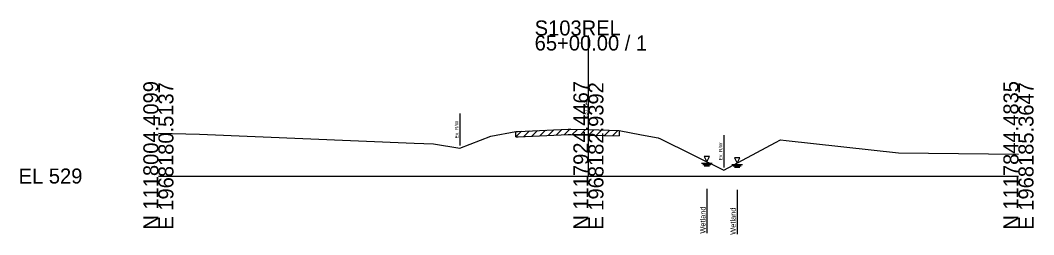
# Model space of a CAD drawing. Extents: x -26 to 163, y -10 to 24518.
# Drawn here: x -25.7 to 162.8, y 13489.1 to 13529 of the extents above; entities that cross this region are included whole.
import ezdxf

# ---------------------------------------------------------------- set-up
doc = ezdxf.new("R2010")
doc.units = 0
for name, color, linetype in [('RD_GPK_XS_Cell', 7, 'Continuous'), ('RD_XS_ExGround', 7, 'Continuous'), ('RD_XS_ExPaveRet', 7, 'Continuous'), ('RD_XS_ExRW', 7, 'Continuous'), ('RD_XS_EXWetland', 7, 'Continuous'), ('RD_XS_TX_Elev_EX', 7, 'Continuous')]:
    doc.layers.add(name, color=color, linetype=linetype)

msp = doc.modelspace()

# ---------------------------------------------------------------- linework, layer by layer
at = {"layer": 'RD_GPK_XS_Cell'}
for p, q in [((80, 13500), (80, 13526.18)), ((0, 13500), (80, 13500)), ((80, 13500), (160, 13500))]:
    msp.add_line(p, q, dxfattribs=at)
at = {"layer": 'RD_XS_ExGround'}
msp.add_lwpolyline([(0, 13507.96), (7.66, 13507.79), (47.56, 13506.15), (51.17, 13505.98), (56.06, 13505.16), (61.87, 13507.4), (66.48, 13508.3), (66.93, 13508.32), (76.24, 13508.73), (76.73, 13508.72), (80, 13508.64), (85.71, 13508.5), (89.89, 13507.7), (93, 13507.09), (93.41, 13506.91), (105.17, 13501.08), (114.83, 13506.25), (115.76, 13506.77), (116.78, 13506.6), (137.7, 13504.3), (160, 13504.08)], dxfattribs=at)
at = {"layer": 'RD_XS_ExPaveRet'}
for p, q in [((67.98, 13507.36), (69.03, 13508.41)), ((69.49, 13507.43), (70.53, 13508.47)), ((70.99, 13507.49), (72.04, 13508.54)), ((72.49, 13507.56), (73.54, 13508.61)), ((73.99, 13507.63), (75.04, 13508.67)), ((75.5, 13507.69), (76.53, 13508.72)), ((77, 13507.71), (77.98, 13508.69)), ((78.5, 13507.68), (79.48, 13508.65)), ((80, 13507.64), (80.98, 13508.62)), ((81.5, 13507.6), (82.48, 13508.58)), ((83.01, 13507.57), (83.98, 13508.54)), ((84.51, 13507.53), (85.49, 13508.51)), ((85.71, 13508.5), (85.71, 13507.5)), ((66.48, 13507.3), (67.53, 13508.34)), ((66.48, 13507.3), (66.48, 13508.3)), ((66.48, 13507.3), (66.93, 13507.32)), ((66.93, 13507.32), (76.24, 13507.73)), ((76.24, 13507.73), (76.73, 13507.72)), ((76.73, 13507.72), (80, 13507.64)), ((80, 13507.64), (85.71, 13507.5))]:
    msp.add_line(p, q, dxfattribs=at)
at = {"layer": 'RD_XS_ExRW'}
for p, q in [((56.07, 13511.66), (56.07, 13505.66)), ((56.07, 13511.66), (56.07, 13505.66)), ((105.19, 13507.58), (105.19, 13501.58))]:
    msp.add_line(p, q, dxfattribs=at)
at = {"layer": 'RD_XS_EXWetland'}
for p, q in [((101.53, 13503.63), (102.03, 13502.63)), ((102.53, 13503.63), (101.53, 13503.63)), ((101.53, 13503.63), (102.03, 13502.63)), ((102.53, 13503.63), (101.53, 13503.63)), ((102.03, 13502.63), (102.53, 13503.63)), ((102.03, 13502.63), (102.53, 13503.63)), ((107.16, 13503.41), (107.66, 13502.41)), ((108.16, 13503.41), (107.16, 13503.41)), ((107.16, 13503.41), (107.66, 13502.41)), ((108.16, 13503.41), (107.16, 13503.41)), ((107.66, 13502.41), (108.16, 13503.41)), ((107.66, 13502.41), (108.16, 13503.41)), ((101.03, 13502.38), (103.03, 13502.38)), ((101.03, 13502.38), (103.03, 13502.38)), ((101.28, 13502.13), (102.78, 13502.13)), ((101.28, 13502.13), (102.78, 13502.13)), ((101.53, 13501.88), (102.53, 13501.88)), ((101.53, 13501.88), (102.53, 13501.88)), ((106.66, 13502.16), (108.66, 13502.16)), ((106.66, 13502.16), (108.66, 13502.16)), ((106.91, 13501.91), (108.41, 13501.91)), ((106.91, 13501.91), (108.41, 13501.91)), ((107.16, 13501.66), (108.16, 13501.66)), ((107.16, 13501.66), (108.16, 13501.66)), ((102.03, 13497.63), (102.03, 13489.38)), ((102.03, 13497.63), (102.03, 13489.38)), ((107.66, 13497.41), (107.66, 13489.16)), ((107.66, 13497.41), (107.66, 13489.16))]:
    msp.add_line(p, q, dxfattribs=at)

# ---------------------------------------------------------------- texts
at = {"layer": 'RD_GPK_XS_Cell'}
for s, p in [('S103REL', (70, 13526.18)), ('65+00.00 / 1', (70, 13523.38)), ('EL 529', (-26, 13498.6))]:
    msp.add_text(s, height=2.8, dxfattribs=at).set_placement(p)
for s, p in [('N 1118004.4099', (0, 13490)), ('E 1968180.5137', (2.8, 13490)), ('N 1117924.4467', (80, 13490)), ('E 1968182.9392', (82.8, 13490)), ('N 1117844.4835', (160, 13490)), ('E 1968185.3647', (162.8, 13490))]:
    msp.add_text(s, height=2.8, rotation=90, dxfattribs=at).set_placement(p)
at = {"layer": 'RD_XS_ExRW'}
for p in [(55.82, 13507), (55.82, 13507), (104.94, 13502.93)]:
    msp.add_text('Ex. R/W ', height=0.65, rotation=90, dxfattribs=at).set_placement(p)
at = {"layer": 'RD_XS_EXWetland'}
for p in [(101.78, 13489.27), (101.78, 13489.27), (107.41, 13489.05), (107.41, 13489.05)]:
    msp.add_text('Wetland ', height=1, rotation=90, dxfattribs=at).set_placement(p)
at = {"layer": 'RD_XS_TX_Elev_EX'}
msp.add_text('537.64', height=0.8, rotation=90, dxfattribs=at).set_placement((79.9, 13510.64))

doc.saveas('drawing.dxf')
